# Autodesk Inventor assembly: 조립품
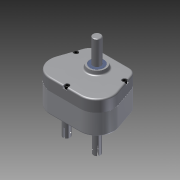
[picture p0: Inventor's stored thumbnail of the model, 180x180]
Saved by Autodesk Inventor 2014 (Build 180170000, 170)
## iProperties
Created: 2014-12
Part Number: 조립품
Document SubType Name: Assembly
Designer: Administrator
Author: Administrator
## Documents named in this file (14)
- C:\Documents and Settings\Administrator\바탕 화면\조립품.iam
- C:\Documents and Settings\Administrator\바탕 화면\본체.ipt
- C:\Documents and Settings\Administrator\바탕 화면\441209v1019\베어링- 6203.ipt
- C:\Documents and Settings\Administrator\바탕 화면\441209v1019\키5x5.ipt
- C:\Documents and Settings\Administrator\바탕 화면\441209v1019\메인축.ipt
- C:\Documents and Settings\Administrator\바탕 화면\441209v1019\메인기어.ipt
- C:\Documents and Settings\Administrator\바탕 화면\441209v1019\멈춤링.ipt
- C:\Documents and Settings\Administrator\바탕 화면\441209v1019\서브기어.ipt
- C:\Documents and Settings\Administrator\바탕 화면\441209v1019\서브축.ipt
- C:\Documents and Settings\Administrator\바탕 화면\441209v1019\커버.ipt
- C:\Documents and Settings\Administrator\바탕 화면\441209v1019\베어링- 6202.ipt
- C:\Documents and Settings\Administrator\바탕 화면\441209v1019\M 5 x 35.ipt
- C:\Documents and Settings\Administrator\바탕 화면\441209v1019\오일시일-D-17.ipt
- C:\Documents and Settings\Administrator\바탕 화면\441209v1019\오일시일-D-15.ipt
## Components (15 placed, 6 different names)
1. KS B 2023 6203 - 17 x 40 x 12:1
2. KS B 2023 6203 - 17 x 40 x 12:2
3. KS B 1336 17 x 1:1
4. KS B 2023 6203 - 17 x 40 x 12:3
5. KS B 2023 6203 - 17 x 40 x 12:4
6. KS B 1336 17 x 1:2
7. KS B 1336 17 x 1:3
8. KS B 2023 6202 - 15 x 35 x 11:1
9. KS B 2023 6202 - 15 x 35 x 11:2
10. KS B 1003 - 미터 M 5 x 35:1
11. KS B 1003 - 미터 M 5 x 35:2
12. KS B 1003 - 미터 M 5 x 35:3
13. KS B 2804 D D - 17 30 8:1
14. KS B 2804 D D - 15 30 7:1
15. KS B 2804 D D - 15 30 7:2
